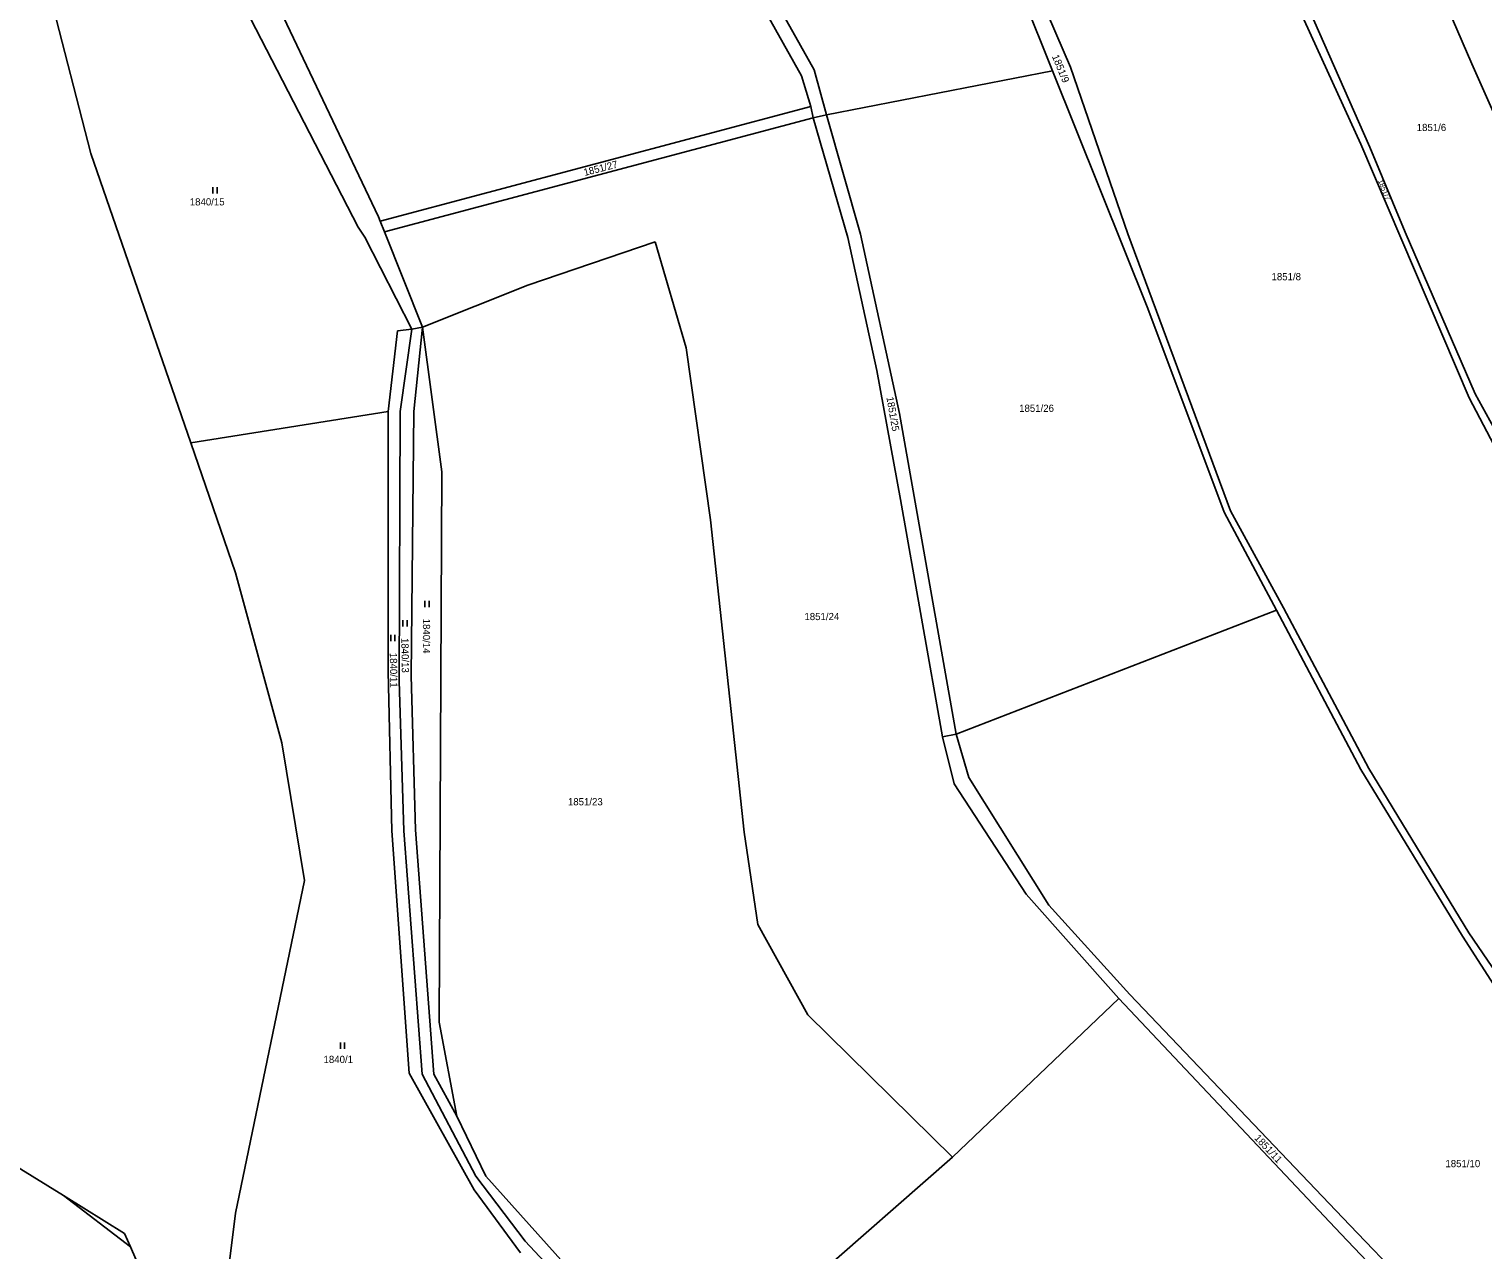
# Model space of a CAD drawing. Extents: x -609861 to -605046, y -1120287 to -1116307.
# Drawn here: x -608197.5 to -607854.5, y -1117471.8 to -1117183.7 of the extents above; entities that cross this region are included whole.
import ezdxf

# ---------------------------------------------------------------- set-up
doc = ezdxf.new("R2010")
doc.units = 0
for name, color, linetype in [('Vrstva 1', 7, 'Continuous'), ('Vrstva 2', 7, 'Continuous'), ('Vrstva 3', 7, 'Continuous'), ('Vrstva 4', 7, 'Continuous')]:
    doc.layers.add(name, color=color, linetype=linetype)

msp = doc.modelspace()

# ---------------------------------------------------------------- linework, layer by layer
at = {"layer": 'Vrstva 1'}
for p, q in [((-608084.25, -1117071.64), (-608015.26, -1117194.78)), ((-608012.3, -1117193.39), (-608060.16, -1117107.77)), ((-607890.38, -1117114.5), (-607857.11, -1117191.98)), ((-607883.31, -1117210.94), (-607921.73, -1117126.5)), ((-607917.88, -1117128.39), (-607881.18, -1117211.63)), ((-607968.09, -1117163.65), (-607956.02, -1117193.62)), ((-607964.89, -1117162.16), (-607951.8, -1117192.76)), ((-608152.04, -1117168.1), (-608119.84, -1117230.48)), ((-608182.93, -1117213.09), (-608192.77, -1117175)), ((-608141.44, -1117172.55), (-608115.09, -1117228.07)), ((-607857.11, -1117191.98), (-607838.01, -1117235.09)), ((-608015.26, -1117194.78), (-608013.08, -1117202.05)), ((-608009.34, -1117203.98), (-608012.3, -1117193.39)), ((-608009.34, -1117203.98), (-607956.02, -1117193.62)), ((-607956.02, -1117193.62), (-607933.54, -1117249.68)), ((-607951.8, -1117192.76), (-607938.27, -1117232.09)), ((-608114.68, -1117229.11), (-608013.08, -1117202.05)), ((-608013.08, -1117202.05), (-608012.53, -1117204.66)), ((-608113.67, -1117231.62), (-608012.53, -1117204.66)), ((-608012.53, -1117204.66), (-608009.34, -1117203.98)), ((-608012.53, -1117204.66), (-608004.35, -1117232.92)), ((-608001.35, -1117232.13), (-608009.34, -1117203.98)), ((-607857.77, -1117270.73), (-607883.31, -1117210.94)), ((-607881.18, -1117211.63), (-607872.81, -1117231.7)), ((-608159.39, -1117281.37), (-608182.93, -1117213.09)), ((-608115.09, -1117228.07), (-608114.68, -1117229.11)), ((-608114.68, -1117229.11), (-608113.67, -1117231.62)), ((-608119.84, -1117230.48), (-608118.34, -1117232.86)), ((-608118.34, -1117232.86), (-608107.18, -1117254.52)), ((-608113.67, -1117231.62), (-608104.71, -1117254.09)), ((-608004.35, -1117232.92), (-607997.48, -1117264.31)), ((-607992.12, -1117274.45), (-608001.35, -1117232.13)), ((-607938.27, -1117232.09), (-607914.02, -1117297.45)), ((-607872.81, -1117231.7), (-607856.28, -1117269.84)), ((-608079.86, -1117244.2), (-608049.82, -1117233.95)), ((-608042.52, -1117258.99), (-608049.82, -1117233.95)), ((-608104.71, -1117254.09), (-608079.86, -1117244.2)), ((-607933.54, -1117249.68), (-607915.51, -1117297.75)), ((-608107.18, -1117254.52), (-608104.71, -1117254.09)), ((-608106.75, -1117273.98), (-608104.71, -1117254.09)), ((-608104.71, -1117254.09), (-608100.17, -1117288.25)), ((-608110.61, -1117254.91), (-608112.76, -1117273.98)), ((-608107.18, -1117254.52), (-608110.61, -1117254.91)), ((-608107.18, -1117254.52), (-608109.97, -1117273.98)), ((-608036.72, -1117299.51), (-608042.52, -1117258.99)), ((-607997.48, -1117264.31), (-607991.9, -1117294.71)), ((-607836.73, -1117310.86), (-607857.77, -1117270.73)), ((-607856.28, -1117269.84), (-607826.02, -1117325.27)), ((-608112.76, -1117273.98), (-608159.39, -1117281.37)), ((-608112.76, -1117273.98), (-608112.76, -1117335.37)), ((-608109.97, -1117273.98), (-608110.18, -1117337.56)), ((-608107.39, -1117336.37), (-608106.75, -1117273.98)), ((-607978.81, -1117350.14), (-607992.12, -1117274.45)), ((-608148.8, -1117312.09), (-608159.39, -1117281.37)), ((-608100.17, -1117288.25), (-608100.79, -1117418.08)), ((-607991.9, -1117294.71), (-607982.03, -1117350.73)), ((-607915.51, -1117297.75), (-607903.16, -1117320.9)), ((-607914.02, -1117297.45), (-607901.57, -1117320.3)), ((-608028.78, -1117373.22), (-608036.72, -1117299.51)), ((-608137.91, -1117352.13), (-608148.8, -1117312.09)), ((-607903.16, -1117320.9), (-607978.81, -1117350.14)), ((-607903.16, -1117320.9), (-607883.33, -1117358.44)), ((-607901.57, -1117320.3), (-607881.39, -1117358.25)), ((-608112.76, -1117335.37), (-608111.9, -1117372.92)), ((-608106.32, -1117372.72), (-608107.39, -1117336.37)), ((-608110.18, -1117337.56), (-608109.11, -1117372.92)), ((-607978.81, -1117350.14), (-607982.03, -1117350.73)), ((-607975.82, -1117360.33), (-607978.81, -1117350.14)), ((-608132.5, -1117384.64), (-608137.91, -1117352.13)), ((-607982.03, -1117350.73), (-607979.24, -1117361.86)), ((-607956.92, -1117390.47), (-607975.82, -1117360.33)), ((-607883.33, -1117358.44), (-607859.29, -1117397.78)), ((-607881.39, -1117358.25), (-607857.78, -1117396.99)), ((-607979.24, -1117361.86), (-607962.28, -1117387.88)), ((-608111.9, -1117372.92), (-608107.82, -1117430.14)), ((-608109.11, -1117372.92), (-608104.81, -1117430.33)), ((-608102.02, -1117430.33), (-608106.32, -1117372.72)), ((-608025.56, -1117395.07), (-608028.78, -1117373.22)), ((-608148.78, -1117463.18), (-608132.5, -1117384.64)), ((-607962.28, -1117387.88), (-607940.39, -1117412.52)), ((-607937.81, -1117411.52), (-607956.92, -1117390.47)), ((-608013.76, -1117416.33), (-608025.56, -1117395.07)), ((-607859.29, -1117397.78), (-607843.62, -1117422.22)), ((-607857.78, -1117396.99), (-607833.1, -1117433.34)), ((-607885.91, -1117466.02), (-607937.81, -1117411.52)), ((-607940.39, -1117412.52), (-607979.63, -1117449.9)), ((-607940.39, -1117412.52), (-607888.05, -1117468)), ((-608100.79, -1117418.08), (-608096.63, -1117440.25)), ((-607979.63, -1117449.9), (-608013.76, -1117416.33)), ((-608107.82, -1117430.14), (-608092.53, -1117457.63)), ((-608104.81, -1117430.33), (-608092.1, -1117454.45)), ((-608096.63, -1117440.25), (-608102.02, -1117430.33)), ((-608096.63, -1117440.25), (-608089.75, -1117454.4)), ((-608200.53, -1117452.12), (-608189.42, -1117459.01)), ((-608043.56, -1117505.89), (-607979.63, -1117449.9)), ((-608092.1, -1117454.45), (-608080.51, -1117469.75)), ((-608089.75, -1117454.4), (-608043.56, -1117505.89)), ((-608189.42, -1117459.01), (-608175, -1117467.95)), ((-608092.53, -1117457.63), (-608081.58, -1117472.53)), ((-608150.45, -1117476.45), (-608148.78, -1117463.18)), ((-607885.91, -1117466.02), (-607841.26, -1117512.3)), ((-608175, -1117467.95), (-608173.63, -1117471.12)), ((-608080.51, -1117469.75), (-608045.31, -1117507.1)), ((-607844.05, -1117514.09), (-607888.05, -1117468)), ((-608173.63, -1117471.12), (-608172.37, -1117474.04))]:
    msp.add_line(p, q, dxfattribs=at)
at = {"layer": 'Vrstva 3'}
for p, q in [((-608154.18, -1117221.01), (-608154.18, -1117222.51)), ((-608153.18, -1117222.51), (-608153.18, -1117221.01)), ((-608104.15, -1117318.68), (-608104.15, -1117320.18)), ((-608103.15, -1117320.18), (-608103.15, -1117318.68)), ((-608109.32, -1117323.2), (-608109.32, -1117324.7)), ((-608108.32, -1117324.7), (-608108.32, -1117323.2)), ((-608112.19, -1117326.69), (-608112.19, -1117328.19)), ((-608111.19, -1117328.19), (-608111.19, -1117326.69)), ((-608124.08, -1117422.9), (-608124.08, -1117424.4)), ((-608123.08, -1117424.4), (-608123.08, -1117422.9))]:
    msp.add_line(p, q, dxfattribs=at)
at = {"layer": 'Vrstva 4'}
msp.add_line((-608189.42, -1117459.01), (-608173.63, -1117471.12), dxfattribs=at)

# ---------------------------------------------------------------- texts
at = {"layer": 'Vrstva 2'}
for s, height, rotation, p in [('1851/9', 1.7, 292.49496, (-607956.22, -1117190.173)), ('1851/27', 1.7, 14.38124, (-608066.44, -1117218.422)), ('1851/7', 1.2, 292.49496, (-607879.284, -1117219.546)), ('1851/25', 1.7, 279.88988, (-607995.243, -1117270.647)), ('1840/14', 1.7, 269.97771, (-608104.6, -1117322.873)), ('1840/13', 1.7, 270.89444, (-608109.694, -1117327.443)), ('1840/11', 1.7, 270.89444, (-608112.414, -1117330.943)), ('1851/11', 1.7, 313.17873, (-607908.531, -1117445.536))]:
    msp.add_text(s, height=height, rotation=rotation, dxfattribs=at).set_placement(p)
for s, p in [('1851/6', (-607870.107, -1117207.81)), ('1840/15', (-608159.607, -1117225.36)), ('1851/8', (-607904.367, -1117243.02)), ('1851/26', (-607963.917, -1117274.07)), ('1851/24', (-608014.577, -1117323.21)), ('1851/23', (-608070.387, -1117366.91)), ('1840/1', (-608128.047, -1117427.72)), ('1851/10', (-607863.337, -1117452.3))]:
    msp.add_text(s, height=1.7, dxfattribs=at).set_placement(p)

doc.saveas('drawing.dxf')
